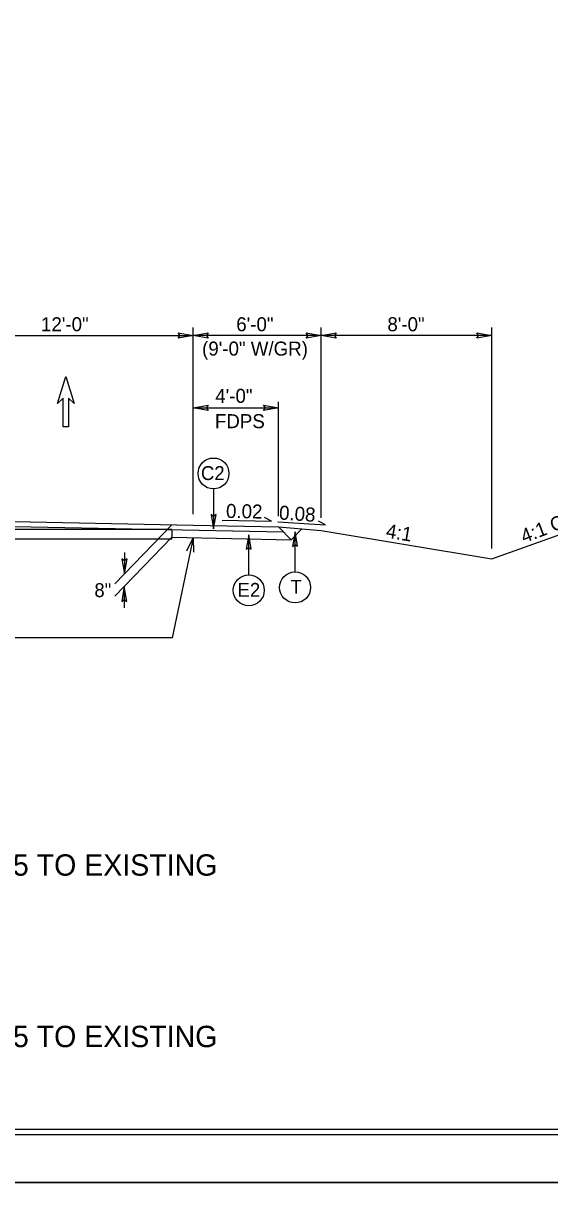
# Model space of a CAD drawing. Extents: x 1901670 to 1902225, y 193498 to 194278.
# Drawn here: x 1902049.2 to 1902073.9, y 193936.9 to 193992.3 of the extents above; entities that cross this region are included whole.
import ezdxf

# ---------------------------------------------------------------- set-up
doc = ezdxf.new("R2010")
doc.units = 0
for name, color, linetype in [('Old_Level_1', 7, 'Continuous'), ('Old_Level_11', 7, 'Continuous'), ('Old_Level_2', 7, 'Continuous'), ('Old_Level_20', 7, 'Continuous'), ('Prop Dimension', 7, 'Continuous'), ('Prop Dimension Text', 7, 'Continuous'), ('Sheet Border Standard 30in CELL', 7, 'Continuous'), ('Sheet Cutting Line CELL', 7, 'Continuous'), ('Sheet Plot Border Inside CELL', 7, 'Continuous'), ('Sheet Plot Border Outside CELL', 7, 'Continuous'), ('Typical Hinge Slope Interstate CELL', 7, 'Continuous'), ('Typical Pavement Slope CELL', 7, 'Continuous'), ('Typical Terminator CELL', 7, 'Continuous')]:
    doc.layers.add(name, color=color, linetype=linetype)

# ---------------------------------------------------------------- blocks, each defined once
blk = doc.blocks.new('TERMINATOR')
at = {"layer": 'Typical Terminator CELL'}
blk.add_lwpolyline([(-0.469, 0.081), (0, 0), (-0.471, -0.083), (-0.411, 0)], close=True, dxfattribs=at)

msp = doc.modelspace()

# ---------------------------------------------------------------- linework, layer by layer
at = {"layer": 'Old_Level_1'}
for p, q in [((1902063.182, 193969.145), (1902063.182, 193978.057)), ((1902039.184, 193969.157), (1902057.182, 193968.797)), ((1902060.852, 193968.987), (1902060.519, 193969.154)), ((1902056.18, 193968.598), (1902022.189, 193968.598)), ((1902039.184, 193968.938), (1902061.405, 193968.493)), ((1902056.18, 193968.817), (1902053.507, 193966.056)), ((1902056.18, 193968.598), (1902056.18, 193968.233)), ((1902057.182, 193968.797), (1902061.182, 193968.717)), ((1902058.537, 193969.036), (1902060.852, 193968.987)), ((1902061.152, 193968.96), (1902063.388, 193968.814)), ((1902061.777, 193968.121), (1902061.182, 193968.717)), ((1902061.182, 193968.717), (1902063.182, 193968.55)), ((1902061.777, 193968.121), (1902062.28, 193968.625)), ((1902063.388, 193968.814), (1902063.063, 193968.995)), ((1902063.182, 193968.55), (1902071.182, 193967.217)), ((1902056.18, 193968.15), (1902022.189, 193968.15)), ((1902056.18, 193968.233), (1902053.509, 193965.475)), ((1902056.18, 193968.233), (1902061.777, 193968.121)), ((1902056.18, 193968.15), (1902056.18, 193968.233)), ((1902053.953, 193967.516), (1902053.953, 193966.516)), ((1902053.951, 193965.931), (1902053.951, 193964.931))]:
    msp.add_line(p, q, dxfattribs=at)
for points in [[(1902057.172, 193968.214), (1902056.19, 193963.522)], [(1902056.878, 193967.604), (1902057.172, 193968.214), (1902057.199, 193967.538)], [(1902056.19, 193963.522), (1902044.068, 193963.522)]]:
    msp.add_lwpolyline(points, dxfattribs=at)
at = {"layer": 'Old_Level_11'}
for p, q in [((1902058.133, 193970.497), (1902058.133, 193968.623)), ((1902059.787, 193966.474), (1902059.787, 193968.348)), ((1902061.959, 193966.608), (1902061.959, 193968.482))]:
    msp.add_line(p, q, dxfattribs=at)
for points in [[(1902058.018, 193969.294), (1902058.133, 193968.623), (1902058.253, 193969.298), (1902058.133, 193969.212)], [(1902059.903, 193967.677), (1902059.787, 193968.348), (1902059.668, 193967.673), (1902059.787, 193967.759)], [(1902062.075, 193967.811), (1902061.959, 193968.482), (1902061.84, 193967.807), (1902061.959, 193967.893)]]:
    msp.add_lwpolyline(points, close=True, dxfattribs=at)
for centre in [(1902058.133, 193971.222), (1902059.787, 193965.749), (1902061.959, 193965.883)]:
    msp.add_circle(centre, 0.725, dxfattribs=at)
at = {"layer": 'Prop Dimension'}
for p, q in [((1902057.182, 193970.365), (1902057.182, 193978.057)), ((1902045.182, 193977.687), (1902057.182, 193977.687))]:
    msp.add_line(p, q, dxfattribs=at)
msp.add_lwpolyline([(1902051.607, 193974.495), (1902051.336, 193974.745), (1902051.336, 193973.411), (1902051.086, 193973.411), (1902051.086, 193974.745), (1902050.815, 193974.495), (1902051.211, 193975.766)], close=True, dxfattribs=at)
msp.add_lwpolyline([(1902051.607, 193974.495), (1902051.336, 193974.745), (1902051.336, 193973.411), (1902051.086, 193973.411), (1902051.086, 193974.745), (1902050.815, 193974.495), (1902051.211, 193975.766)], close=True, dxfattribs=at)
at = {"layer": 'Prop Dimension Text'}
for p, q in [((1902057.182, 193969.313), (1902057.182, 193978.057)), ((1902071.182, 193967.708), (1902071.182, 193978.057)), ((1902063.182, 193977.687), (1902057.182, 193977.687)), ((1902071.182, 193977.687), (1902063.182, 193977.687)), ((1902057.182, 193974.301), (1902061.182, 193974.301)), ((1902061.182, 193969.223), (1902061.182, 193974.583))]:
    msp.add_line(p, q, dxfattribs=at)
at = {"layer": 'Sheet Border Standard 30in CELL'}
msp.add_lwpolyline([(1902132.544, 194045.514), (1901982.544, 194045.514), (1901982.544, 193940.514), (1902132.544, 193940.514)], close=True, dxfattribs=at)
at = {"layer": 'Sheet Cutting Line CELL'}
for p, q in [((1901965.844, 193938.014), (1902134.244, 193938.014)), ((1902134.244, 193938.014), (1901965.844, 193938.014))]:
    msp.add_line(p, q, dxfattribs=at)
at = {"layer": 'Sheet Plot Border Inside CELL'}
msp.add_lwpolyline([(1902133.794, 194045.769), (1901967.144, 194045.769), (1901967.144, 193940.259), (1902133.794, 193940.259)], close=True, dxfattribs=at)
at = {"layer": 'Sheet Plot Border Outside CELL'}
for points in [[(1902134.244, 194048.014), (1901965.844, 194048.014), (1901965.844, 193938.014), (1902134.244, 193938.014)], [(1902134.244, 193938.014), (1901965.844, 193938.014), (1901965.844, 193828.014), (1902134.244, 193828.014)]]:
    msp.add_lwpolyline(points, close=True, dxfattribs=at)
at = {"layer": 'Typical Pavement Slope CELL'}
msp.add_line((1902071.182, 193967.217), (1902080.275, 193970.492), dxfattribs=at)

# ---------------------------------------------------------------- block references
at = {"layer": 'Old_Level_1', "xscale": 1.5, "yscale": -1.5}
for p, rotation in [((1902053.953, 193966.516), -90), ((1902053.951, 193965.931), 90.00000000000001)]:
    msp.add_blockref('TERMINATOR', p, dxfattribs=dict(at, rotation=rotation))
at = {"layer": 'Prop Dimension', "xscale": 1.5, "yscale": 1.5}
for p in [(1902057.182, 193977.687), (1902063.182, 193977.687), (1902071.182, 193977.687), (1902061.182, 193974.301)]:
    msp.add_blockref('TERMINATOR', p, dxfattribs=at)
at = {"layer": 'Prop Dimension', "xscale": 1.5, "yscale": 1.5, "rotation": 180}
for p in [(1902057.182, 193977.687), (1902063.182, 193977.687), (1902057.182, 193974.301)]:
    msp.add_blockref('TERMINATOR', p, dxfattribs=at)

# ---------------------------------------------------------------- texts
at = {"layer": 'Old_Level_1'}
msp.add_text('4:1 OR FLATTER', height=0.656, rotation=20.8342, dxfattribs=at).set_placement((1902072.691, 193967.947))
msp.add_text('8"', height=0.6491, dxfattribs=at).set_placement((1902052.547, 193965.433))
at = {"layer": 'Old_Level_11'}
for p in [(1902020.941, 193952.382), (1902020.941, 193944.35)]:
    msp.add_text('TRANSITION FROM TYPICAL SECTION NO. 5 TO EXISTING', height=1, dxfattribs=at).set_placement(p)
at = {"layer": 'Old_Level_2'}
for s, rotation, p in [('0.02', 358.8084, (1902058.714, 193969.143)), ('0.08', 356.2834, (1902061.189, 193969.068))]:
    msp.add_text(s, height=0.656, rotation=rotation, dxfattribs=at).set_placement(p)
at = {"layer": 'Old_Level_20'}
for s, height, p in [('C2', 0.6491, (1902057.544, 193970.916)), ('E2', 0.6491, (1902059.261, 193965.445)), ('T', 0.649, (1902061.748, 193965.59))]:
    msp.add_text(s, height=height, dxfattribs=at).set_placement(p)
at = {"layer": 'Prop Dimension'}
for s, p in [('12\'-0" ', (1902050.044, 193977.885)), ('8\'-0" ', (1902066.285, 193977.885))]:
    msp.add_text(s, height=0.656, dxfattribs=at).set_placement(p)
at = {"layer": 'Prop Dimension Text'}
for s, p in [('6\'-0"', (1902059.2, 193977.885)), ('(9\'-0" W/GR)', (1902057.598, 193976.745)), ('FDPS', (1902058.198, 193973.345))]:
    msp.add_text(s, height=0.656, dxfattribs=at).set_placement(p)
msp.add_text('4\'-0"', height=0.656, rotation=360, dxfattribs=at).set_placement((1902058.215, 193974.53))
at = {"layer": 'Typical Hinge Slope Interstate CELL'}
msp.add_text('4:1', height=0.656, rotation=350.5377, dxfattribs=at).set_placement((1902066.184, 193968.228))

doc.saveas('drawing.dxf')
